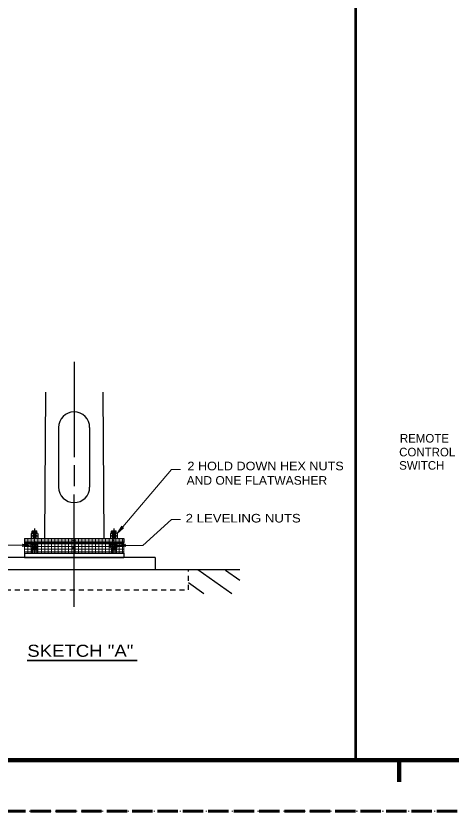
# Model space of a CAD drawing. Extents: x 312583 to 312854, y 144419 to 144597.
# Drawn here: x 312693.4 to 312732, y 144418.6 to 144489 of the extents above; entities that cross this region are included whole.
import ezdxf
from ezdxf.enums import TextEntityAlignment as Align

# ---------------------------------------------------------------- set-up
doc = ezdxf.new("R2010")
doc.units = 0
doc.header["$LTSCALE"] = 0.3
for name, pattern in [('DOTTED', [1.5, 0.3, -1.2]), ('LONG_DASHED', [7.5, 6, -1.5]), ('SHORT_DASHED', [2.7, 1.5, -1.2])]:
    doc.linetypes.add(name, pattern=pattern)
for name, color, linetype, lineweight in [('1', 7, 'Continuous', 13), ('2', 7, 'Continuous', 13), ('61', 7, 'LONG_DASHED', 60), ('63', 7, 'DOTTED', 13)]:
    doc.layers.add(name, color=color, linetype=linetype, lineweight=lineweight)

msp = doc.modelspace()

# ---------------------------------------------------------------- linework, layer by layer
at = {"layer": '1', "lineweight": 53}
msp.add_line((312723.5031, 144491.5236), (312723.5031, 144423.0846), dxfattribs=at)
at = {"layer": '1'}
for p, q in [((312694.1598, 144442.4824), (312702.9534, 144442.4824)), ((312694.1598, 144442.352), (312694.1598, 144441.4014)), ((312694.4588, 144442.7124), (312694.4588, 144441.4014)), ((312694.7578, 144442.7124), (312694.7578, 144441.4014)), ((312695.0568, 144442.7124), (312695.0568, 144441.4014)), ((312695.3558, 144442.7124), (312695.3558, 144441.4014)), ((312695.6548, 144442.7124), (312695.6548, 144441.4014)), ((312695.9538, 144442.7124), (312695.9538, 144441.4014)), ((312696.2528, 144442.7124), (312696.2528, 144441.4014)), ((312696.5518, 144442.7124), (312696.5518, 144441.4014)), ((312696.8584, 144442.7124), (312696.8584, 144441.4014)), ((312697.1574, 144442.7124), (312697.1574, 144441.4014)), ((312697.4564, 144442.7124), (312697.4564, 144441.4014)), ((312697.7554, 144442.7124), (312697.7554, 144441.4014)), ((312698.0544, 144442.7124), (312698.0544, 144441.4014)), ((312698.3534, 144442.7124), (312698.3534, 144441.4014)), ((312698.6524, 144442.7124), (312698.6524, 144441.4014)), ((312698.9514, 144442.7124), (312698.9514, 144441.4014)), ((312699.2504, 144442.7124), (312699.2504, 144441.4014)), ((312699.5494, 144442.7124), (312699.5494, 144441.4014)), ((312699.8484, 144442.7124), (312699.8484, 144441.4014)), ((312700.1474, 144442.7124), (312700.1474, 144441.4014)), ((312700.4464, 144442.7124), (312700.4464, 144441.4014)), ((312700.7454, 144442.7124), (312700.7454, 144441.4014)), ((312701.0444, 144442.7124), (312701.0444, 144441.4014)), ((312701.3434, 144442.7124), (312701.3434, 144441.4014)), ((312701.6501, 144442.7124), (312701.6501, 144441.4014)), ((312701.9491, 144442.7124), (312701.9491, 144441.4014)), ((312702.2481, 144442.7124), (312702.2481, 144441.4014)), ((312702.5471, 144442.7124), (312702.5471, 144441.4014)), ((312702.8461, 144442.7124), (312702.8461, 144441.4014)), ((312702.9534, 144442.352), (312702.9534, 144441.4014)), ((312694.1598, 144442.2447), (312702.9534, 144442.2447)), ((312694.1598, 144442.007), (312702.9534, 144442.007)), ((312694.1598, 144441.7617), (312702.9534, 144441.7617)), ((312694.1598, 144441.524), (312702.9534, 144441.524))]:
    msp.add_line(p, q, dxfattribs=at)
at = {"layer": '1', "lineweight": 25}
for p, q in [((312705.7518, 144441.041), (312691.3691, 144441.041)), ((312705.7518, 144441.041), (312705.7518, 144439.9447)), ((312713.2344, 144439.9447), (312683.8558, 144439.9447))]:
    msp.add_line(p, q, dxfattribs=at)
at = {"layer": '1', "lineweight": 158}
for p, q in [((312616.5, 144423.0846), (312849, 144423.0846)), ((312727.35, 144421.1646), (312727.35, 144423.0846))]:
    msp.add_line(p, q, dxfattribs=at)
at = {"layer": '1', "linetype": 'SHORT_DASHED', "lineweight": 25}
msp.add_lwpolyline([(312688.4481, 144438.1584), (312708.6958, 144438.1584), (312708.6958, 144439.9447)], dxfattribs=at)
at = {"layer": '1', "lineweight": 25}
for centre, radius in [((312698.5554, 144442.5211), 0.0871), ((312698.5554, 144442.5211), 0.0552), ((312698.5494, 144441.8446), 0.0871), ((312698.5494, 144441.8446), 0.0552)]:
    msp.add_circle(centre, radius, dxfattribs=at)
at = {"layer": '2', "lineweight": 25}
for p, q in [((312698.5604, 144458.3524), (312698.5604, 144449.9037)), ((312696.0228, 144455.6767), (312695.9308, 144442.7124)), ((312701.0981, 144455.6767), (312701.1901, 144442.7124)), ((312697.1804, 144452.541), (312697.1804, 144447.2664)), ((312699.9328, 144452.541), (312699.9328, 144447.2664)), ((312698.5604, 144449.2137), (312698.5604, 144447.3584)), ((312698.5604, 144436.6557), (312698.5604, 144446.607)), ((312694.8344, 144443.3717), (312694.8651, 144443.4024)), ((312694.8344, 144443.341), (312695.2561, 144443.341)), ((312694.8344, 144443.3104), (312695.2561, 144443.3104)), ((312694.8344, 144443.2874), (312695.2561, 144443.2874)), ((312694.8344, 144443.2567), (312695.2561, 144443.2567)), ((312694.8344, 144443.226), (312695.2561, 144443.226)), ((312694.8344, 144443.1954), (312695.2561, 144443.1954)), ((312694.8651, 144443.4024), (312695.2254, 144443.4024)), ((312694.9264, 144443.1647), (312694.9264, 144442.9577)), ((312695.0414, 144443.6017), (312695.0414, 144442.6587)), ((312695.1641, 144443.1647), (312695.1641, 144442.9577)), ((312695.2254, 144443.4024), (312695.2561, 144443.3717)), ((312695.2561, 144443.1954), (312695.2561, 144443.3717)), ((312695.3404, 144443.1647), (312695.3404, 144442.9577)), ((312701.8648, 144443.3717), (312701.8954, 144443.4024)), ((312701.8648, 144443.341), (312702.2864, 144443.341)), ((312701.8648, 144443.3104), (312702.2864, 144443.3104)), ((312701.8648, 144443.2874), (312702.2864, 144443.2874)), ((312701.8648, 144443.2567), (312702.2864, 144443.2567)), ((312701.8648, 144443.226), (312702.2864, 144443.226)), ((312701.8648, 144443.1954), (312702.2864, 144443.1954)), ((312701.8954, 144443.4024), (312702.2558, 144443.4024)), ((312701.9568, 144443.1647), (312701.9568, 144442.9577)), ((312702.0718, 144443.6017), (312702.0718, 144442.6587)), ((312702.1944, 144443.1647), (312702.1944, 144442.9577)), ((312702.2558, 144443.4024), (312702.2864, 144443.3717)), ((312702.2864, 144443.1954), (312702.2864, 144443.3717)), ((312702.3708, 144443.1647), (312702.3708, 144442.9577)), ((312694.1598, 144442.7124), (312702.9534, 144442.7124)), ((312694.1598, 144442.7124), (312694.1598, 144442.352)), ((312694.1598, 144442.352), (312702.9534, 144442.352)), ((312694.7424, 144442.927), (312694.7424, 144442.7124)), ((312694.7424, 144442.145), (312694.7424, 144442.352)), ((312694.9264, 144442.927), (312694.9264, 144442.7124)), ((312694.9264, 144442.145), (312694.9264, 144442.352)), ((312695.0414, 144442.4747), (312695.0414, 144442.5974)), ((312695.0414, 144442.4134), (312695.0414, 144441.4014)), ((312695.1641, 144442.927), (312695.1641, 144442.7124)), ((312695.1641, 144442.145), (312695.1641, 144442.352)), ((312695.3404, 144442.927), (312695.3404, 144442.7124)), ((312695.3404, 144442.145), (312695.3404, 144442.352)), ((312701.7728, 144442.927), (312701.7728, 144442.7124)), ((312701.7728, 144442.145), (312701.7728, 144442.352)), ((312701.9568, 144442.927), (312701.9568, 144442.7124)), ((312701.9568, 144442.145), (312701.9568, 144442.352)), ((312702.0718, 144442.4747), (312702.0718, 144442.5974)), ((312702.1944, 144442.927), (312702.1944, 144442.7124)), ((312702.1944, 144442.145), (312702.1944, 144442.352)), ((312702.3708, 144442.927), (312702.3708, 144442.7124)), ((312702.3708, 144442.145), (312702.3708, 144442.352)), ((312702.9534, 144442.7124), (312702.9534, 144442.352)), ((312694.7424, 144441.9074), (312694.7424, 144442.1144)), ((312695.2561, 144441.8767), (312694.8344, 144441.8767)), ((312694.8344, 144441.8767), (312694.8344, 144441.4014)), ((312695.2561, 144441.846), (312694.8344, 144441.846)), ((312695.2561, 144441.8154), (312694.8344, 144441.8154)), ((312695.2561, 144441.7847), (312694.8344, 144441.7847)), ((312695.2561, 144441.754), (312694.8344, 144441.754)), ((312695.2561, 144441.7234), (312694.8344, 144441.7234)), ((312695.2561, 144441.7004), (312694.8344, 144441.7004)), ((312695.2561, 144441.6697), (312694.8344, 144441.6697)), ((312694.9264, 144441.9074), (312694.9264, 144442.1144)), ((312695.1641, 144441.9074), (312695.1641, 144442.1144)), ((312695.2561, 144441.8767), (312695.2561, 144441.4014)), ((312701.7728, 144441.9074), (312701.7728, 144442.1144)), ((312702.2864, 144441.8767), (312701.8648, 144441.8767)), ((312701.8648, 144441.8767), (312701.8648, 144441.4014)), ((312702.2864, 144441.846), (312701.8648, 144441.846)), ((312702.2864, 144441.8154), (312701.8648, 144441.8154)), ((312702.2864, 144441.7847), (312701.8648, 144441.7847)), ((312702.2864, 144441.754), (312701.8648, 144441.754)), ((312702.2864, 144441.7234), (312701.8648, 144441.7234)), ((312702.2864, 144441.7004), (312701.8648, 144441.7004)), ((312702.2864, 144441.6697), (312701.8648, 144441.6697)), ((312701.9568, 144441.9074), (312701.9568, 144442.1144)), ((312702.1944, 144441.9074), (312702.1944, 144442.1144)), ((312702.2864, 144441.8767), (312702.2864, 144441.4014)), ((312694.1598, 144441.4014), (312702.9534, 144441.4014)), ((312694.1598, 144441.4014), (312694.1598, 144441.041)), ((312694.1598, 144441.041), (312702.9534, 144441.041)), ((312702.9534, 144441.4014), (312702.9534, 144441.041)), ((312712.5214, 144437.8134), (312709.5314, 144439.9447)), ((312713.2344, 144438.9864), (312711.9848, 144439.8757)), ((312710.0681, 144437.8134), (312708.6958, 144438.7794))]:
    msp.add_line(p, q, dxfattribs=at)
at = {"layer": '2'}
for p, q in [((312707.2008, 144448.8074), (312702.3708, 144443.1647)), ((312707.2008, 144448.8074), (312707.9981, 144448.8074)), ((312707.1854, 144444.4067), (312707.9904, 144444.4067)), ((312702.0718, 144442.7124), (312702.0718, 144441.4014))]:
    msp.add_line(p, q, dxfattribs=at)
at = {"layer": '2', "lineweight": 35}
msp.add_line((312694.4038, 144431.9254), (312704.1426, 144431.9254), dxfattribs=at)
at = {"layer": '2'}
for points in [[(312694.7271, 144442.1144), (312691.8828, 144442.1144), (312686.6848, 144445.5337)], [(312702.3861, 144442.099), (312704.6401, 144442.099), (312707.1854, 144444.4067)]]:
    msp.add_lwpolyline(points, dxfattribs=at)
for points in [[(312702.9228, 144443.663), (312702.3708, 144443.1647), (312702.7771, 144443.7934), (312702.8078, 144443.6707)], [(312693.9911, 144442.2064), (312694.7271, 144442.1144), (312693.9911, 144442.0147), (312694.0601, 144442.1144)], [(312703.1221, 144442.007), (312702.3861, 144442.099), (312703.1221, 144442.2064), (312703.0531, 144442.099)]]:
    msp.add_lwpolyline(points, close=True, dxfattribs=at)
at = {"layer": '2', "lineweight": 25}
for points in [[(312694.7424, 144443.1647), (312694.7424, 144442.9577), (312695.3404, 144442.9577)], [(312694.8344, 144443.1954), (312694.8344, 144443.3717), (312695.2561, 144443.3717)], [(312701.7728, 144443.1647), (312701.7728, 144442.9577), (312702.3708, 144442.9577)], [(312701.8648, 144443.1954), (312701.8648, 144443.3717), (312702.2864, 144443.3717)], [(312695.3404, 144441.9074), (312695.3404, 144442.1144), (312694.7424, 144442.1144)], [(312702.3708, 144441.9074), (312702.3708, 144442.1144), (312701.7728, 144442.1144)]]:
    msp.add_lwpolyline(points, dxfattribs=at)
for centre, radius, start, end in [((312698.5581, 144452.54), 1.3776, 0, 180), ((312698.5581, 144447.2692), 1.3776, 180, 0), ((312694.834, 144443.0446), 0.1497, 53.1301, 126.8699), ((312695.0437, 144442.9398), 0.2546, 61.92751, 118.07249), ((312695.2533, 144443.0446), 0.1497, 53.1301, 126.8699), ((312701.8639, 144443.0446), 0.1497, 53.1301, 126.8699), ((312702.0735, 144442.9398), 0.2546, 61.92751, 118.07249), ((312702.2832, 144443.0446), 0.1497, 53.1301, 126.8699), ((312694.834, 144442.805), 0.1497, 53.1301, 126.8699), ((312695.0437, 144442.7002), 0.2546, 61.92751, 118.07249), ((312695.2533, 144442.805), 0.1497, 53.1301, 126.8699), ((312701.8639, 144442.805), 0.1497, 53.1301, 126.8699), ((312702.0735, 144442.7002), 0.2546, 61.92751, 118.07249), ((312702.2832, 144442.805), 0.1497, 53.1301, 126.8699), ((312694.834, 144442.2659), 0.1497, 233.1301, 306.8699), ((312694.834, 144442.0264), 0.1497, 233.1301, 306.8699), ((312695.0437, 144442.3708), 0.2546, 241.92751, 298.07249), ((312695.0437, 144442.1312), 0.2546, 241.92751, 298.07249), ((312695.2533, 144442.2659), 0.1497, 233.1301, 306.8699), ((312695.2533, 144442.0264), 0.1497, 233.1301, 306.8699), ((312701.8639, 144442.2659), 0.1497, 233.1301, 306.8699), ((312701.8639, 144442.0264), 0.1497, 233.1301, 306.8699), ((312702.0735, 144442.3708), 0.2546, 241.92751, 298.07249), ((312702.0735, 144442.1312), 0.2546, 241.92751, 298.07249), ((312702.2832, 144442.2659), 0.1497, 233.1301, 306.8699), ((312702.2832, 144442.0264), 0.1497, 233.1301, 306.8699)]:
    msp.add_arc(centre, radius, start, end, dxfattribs=at)
at = {"layer": '61'}
msp.add_line((312851.75, 144418.5846), (312583.526, 144418.5846), dxfattribs=at)
at = {"layer": '63'}
msp.add_lwpolyline([(312601.2, 144418.5846), (312853.5, 144418.5846), (312853.5, 144596.7846)], dxfattribs=at)

# ---------------------------------------------------------------- texts
at = {"layer": '1'}
for s, p in [('REMOTE', (312727.4264, 144451.2051)), ('CONTROL', (312727.3632, 144449.982)), ('SWITCH', (312727.3632, 144448.8039))]:
    msp.add_text(s, height=0.76, dxfattribs=at).set_placement(p)
at = {"layer": '2'}
for s, width, p in [('2 HOLD DOWN HEX NUTS', 1.1, (312708.6003, 144448.7494)), ('AND ONE FLATWASHER', 1.05, (312708.5302, 144447.4757)), ('2 LEVELING NUTS', 1.15, (312708.4449, 144444.1307))]:
    msp.add_text(s, height=0.76, dxfattribs=dict(at, width=width)).set_placement(p)
at = {"layer": '2', "width": 1.15}
msp.add_text('SKETCH "A"', height=1.07, dxfattribs=at).set_placement((312699.1096, 144432.2418), align=Align.CENTER)

doc.saveas('drawing.dxf')
